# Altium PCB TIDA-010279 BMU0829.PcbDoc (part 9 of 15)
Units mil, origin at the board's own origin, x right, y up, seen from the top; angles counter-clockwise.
Board outline 11269.69 x 4438.98 mil, 4 copper layers (Top Layer, Signal Layer 1, Signal Layer 2, Bottom Layer), stack 61.6 mil thick; 1494 components, 725 nets, 3766 pads, 2728 vias.
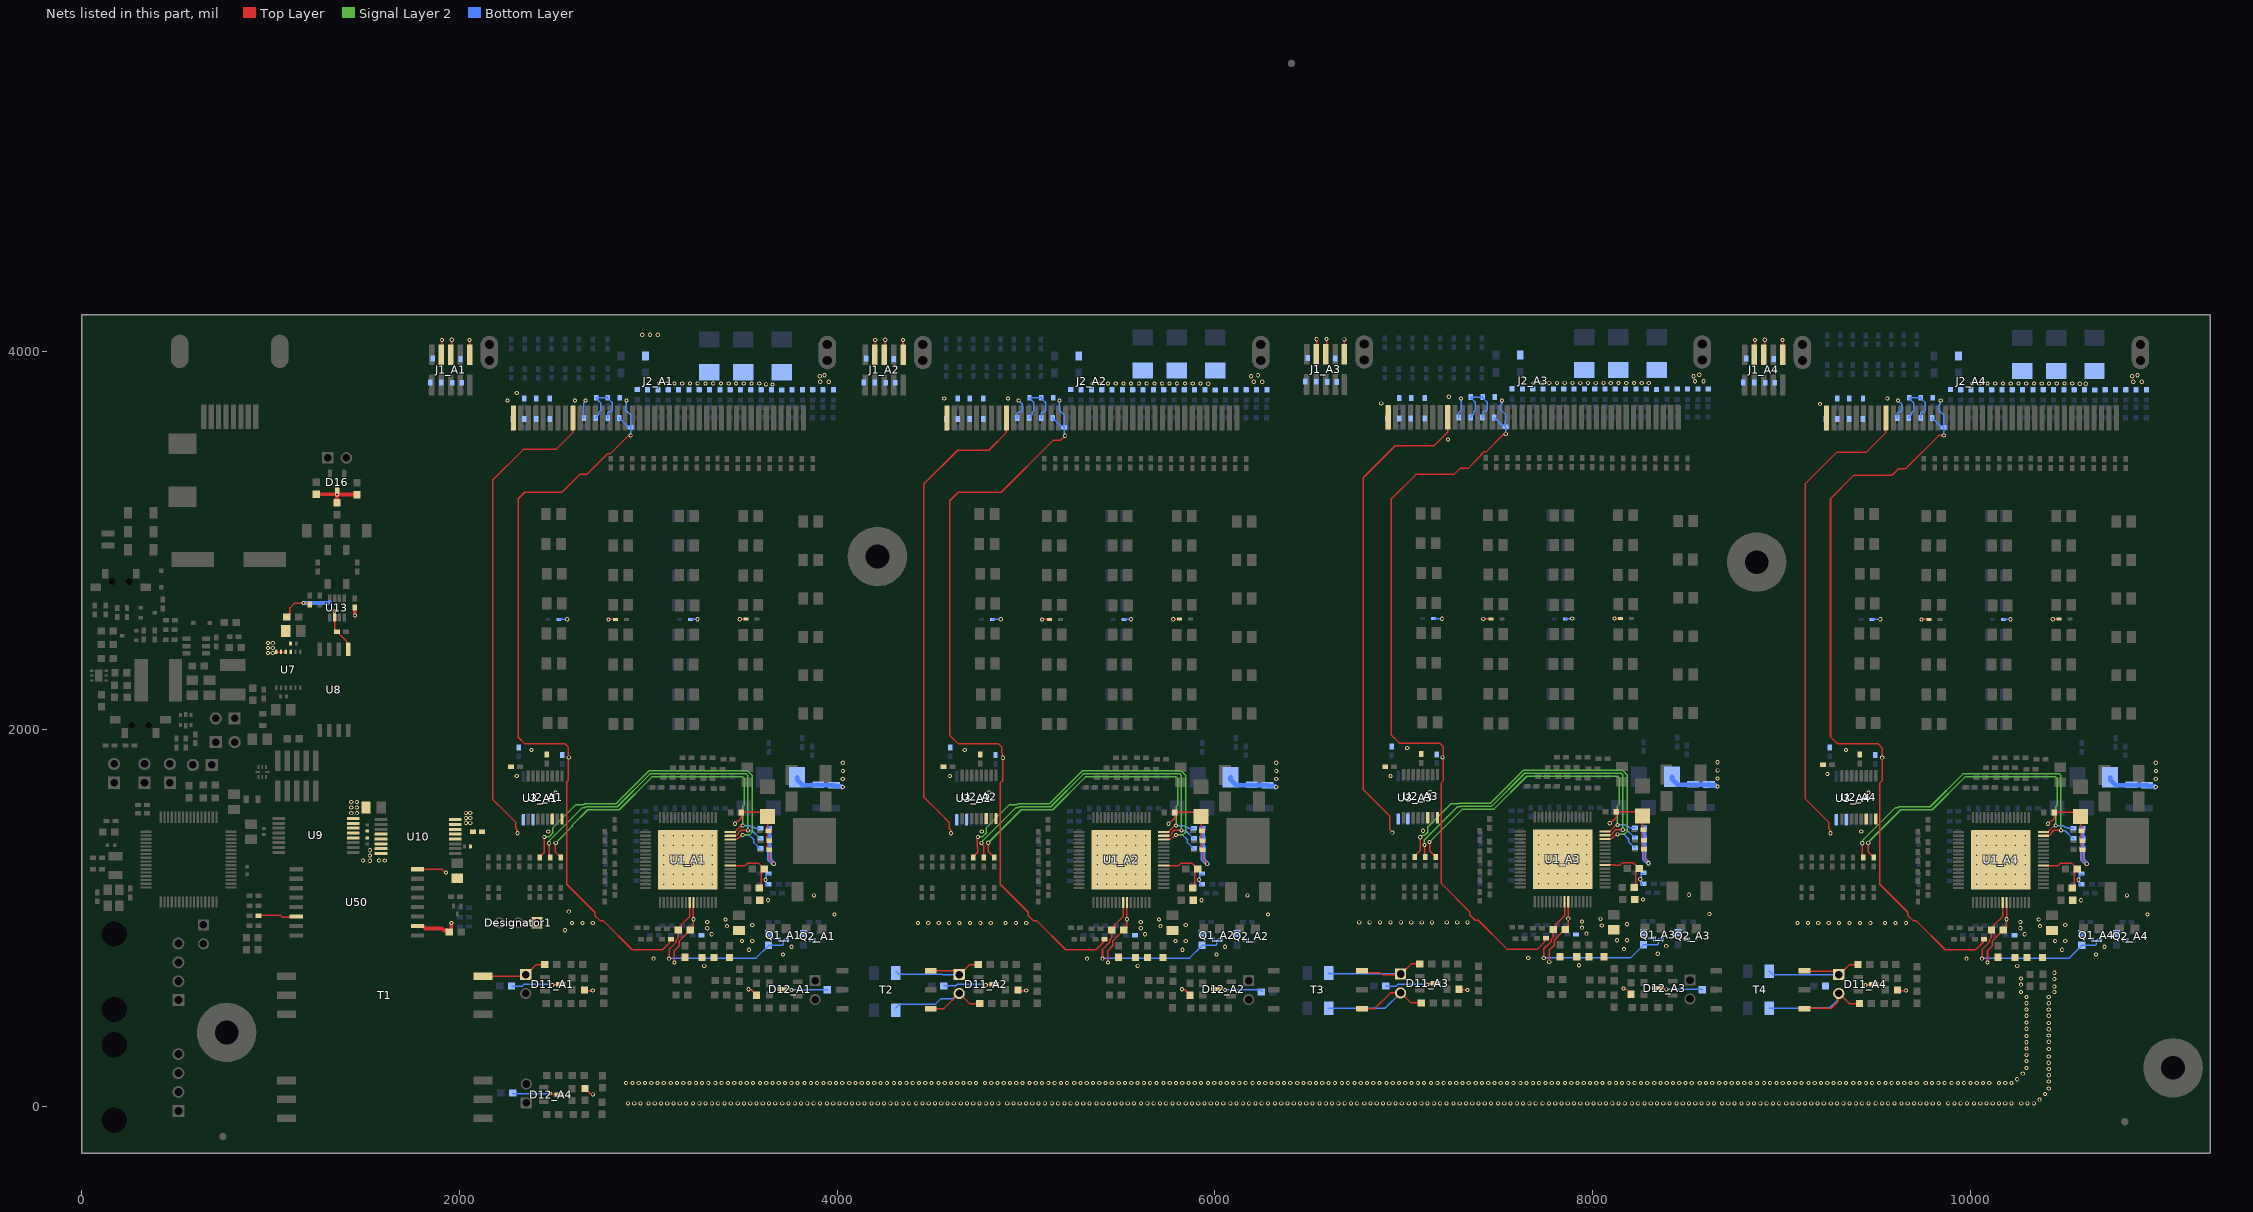
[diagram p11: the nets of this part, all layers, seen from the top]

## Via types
v1: diameter 22.01, hole 12.01, Top Layer to Bottom Layer, tented both sides, 2578 vias
v2: diameter 19.68, hole 7.87, Top Layer to Bottom Layer, tented both sides, 144 vias
v3: diameter 92.52, hole 49.21, Top Layer to Bottom Layer, 4 vias
v4: diameter 19.68, hole 7.87, Top Layer to Bottom Layer, 2 vias

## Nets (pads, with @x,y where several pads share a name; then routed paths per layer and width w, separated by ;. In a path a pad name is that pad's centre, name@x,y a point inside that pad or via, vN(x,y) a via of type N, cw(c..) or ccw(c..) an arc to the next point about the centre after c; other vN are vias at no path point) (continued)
COMML_N_OPT_A2: C163.2 J3_A2.2 R190_A2.1 T2.4 | length 683.8
  Top Layer w8: T2.4@4495.57,520.08 4565.69,520.08 4645.67,600.06 J3_A2.2@4645.67,600.39 ; J3_A2.2@4646.9,600.87 4701.1,546.67 R190_A2.1@4755.58,546.67
  Bottom Layer w8: C163.2@4311.02,521.65 4311.02,524.61 4330.65,544.23 4520.61,544.23 4549.52,573.15 4614.27,573.15 4641.39,600.27 J3_A2.2@4645.87,600.27
COMML_N_OPT_A3: C164.2 J3_A3.2 R190_A3.1 T3.4 | length 789.4
  Top Layer w8: T3.4@6779.04,520.08 6845.75,520.08 6929.15,603.48 6975.26,603.48 J3_A3.2@6978.35,600.39 ; J3_A3.2@6983.49,604.08 7037.7,549.88 R190_A3.1@7092.18,549.88
  Bottom Layer w8: C164.2@6602.36,521.65 6900.65,521.65 J3_A3.2@6982.47,603.48 6988.19,609.19 J3_A3.2@6988.19,610.24
COMML_N_OPT_A4: C165.2 J3_A4.2 R190_A4.1 T4.4 | length 798.4
  Top Layer w8: T4.4@9121.56,520.08 9123.13,521.65 9263.23,521.65 9300.31,558.74 9300.31,599.53 J3_A4.2@9311.02,610.24 ; J3_A4.2@9303.72,600.87 9357.93,546.67 R190_A4.1@9412.41,546.67
  Bottom Layer w8: C165.2@8935.04,521.65 9251.97,521.65 9295.28,564.96 9295.28,592.84 J3_A4.2@9302.7,600.27
COMML_P_OPT_A1: J3_A1.1 R177_A1.1 T1.6 | length 343
  Top Layer w8: T1.6@2135.83,688.98 2137.57,690.71 2341.32,690.71 J3_A1.1@2350.88,700.27 ; J3_A1.1@2351.24,700.63 2376.4,725.8 2379.34,725.8 2406.91,753.36 R177_A1.1@2452.69,753.36
COMML_P_OPT_A2: C153.1 J3_A2.1 R177_A2.1 T2.6 | length 621.1
  Top Layer w8: T2.6@4495.57,720.08 4620.35,720.08 4635.83,704.6 J3_A2.1@4635.83,698.82 ; J3_A2.1@4646.25,697.69 4646.25,700.63 4671.42,725.8 4674.36,725.8 4701.92,753.36 R177_A2.1@4747.7,753.36
  Bottom Layer w8: C153.1@4311.02,718.5 4327.52,702.01 4553.89,702.01 4555.64,700.27 J3_A2.1@4645.87,700.27
COMML_P_OPT_A3: C154.1 J3_A3.1 R177_A3.1 T3.6 | length 734.1
  Top Layer w8: T3.6@6779.04,720.08 6788.05,711.06 6874.5,711.06 6886.74,698.82 J3_A3.1@6988.19,698.82 ; J3_A3.1@6982.85,700.9 6982.85,703.84 7008.02,729 7010.95,729 7038.52,756.57 R177_A3.1@7084.3,756.57
  Bottom Layer w8: C154.1@6602.36,708.66 6607.55,703.48 J3_A3.1@6982.47,703.48 6983.53,703.48 J3_A3.1@6988.19,698.82
COMML_P_OPT_A4: C155.1 J3_A4.1 R177_A4.1 T4.6 | length 699.9
  Top Layer w8: T4.6@9121.56,720.08 9124.24,717.4 9282.6,717.4 J3_A4.1@9311.02,688.98 ; J3_A4.1@9303.08,700.63 9328.25,725.8 9331.18,725.8 9358.75,753.36 R177_A4.1@9404.53,753.36
  Bottom Layer w8: C155.1@8935.04,718.5 8953.27,700.27 9299.73,700.27 J3_A4.1@9301.18,698.82
DDGND: C202.2 C203.1 C204.2 C218.2 C219.2 C220.1 C221.1 C222.2 D16.3 R256.2 U7.9 U7.10 U7.11 U7.12 U8.5 U13.2 | length 958.1
  Top Layer w8: U7.12@1029.53,2408.32 1029.53,2408.07 1031.44,2406.16 1053.22,2406.16 1055.12,2408.07 U7.11@1055.12,2408.32 ; U7.11@1055.78,2405.95 1055.99,2406.16 1078.81,2406.16 1080.72,2408.07 U7.10@1080.72,2408.32 ; C204.2@1079.53,2504.6 C204.2@1079.53,2518.39 C204.2@1079.53,2524.89 ; C202.2@1086.46,2593.41 1087.45,2593.41 1102.15,2608.11 1102.15,2641.33 1127.09,2666.27 1173.55,2666.27 v1(1174.7,2667.42) 1199.36,2667.42 R256.2@1206.74,2660.04 ; v1@1338.81,2623.74 U13.2@1338.81,2590.08 1338.81,2528.26 1339.7,2527.37 1339.7,2523.44 1347.51,2515.62 C220.1@1351.45,2515.62 1355.39,2515.62 1363.2,2507.81 1363.2,2503.88 1402.39,2464.68 1402.39,2429.72 U8.5@1410.2,2421.91 ; C219.2@1359.32,3206.27 1368.2,3197.4 C219.2@1368.2,3196.41
  Top Layer w20: C204.2@1079.53,2504.6 C204.2@1086.06,2498.06 ; C218.2@1241.81,3243.07 1343.55,3243.07 1351.97,3251.49 D16.3@1351.97,3259.37 ; v1(1338.49,2624.06) v1@1338.81,2623.74 ; v1(1351.61,3241.65) 1351.79,3241.83 1351.79,3241.65 D16.3@1351.97,3241.65 ; C219.2@1351.97,3198.92 D16.3@1351.97,3241.65 ; v1(1446.1,2601.44) C222.2@1446.1,2644.37 ; C221.1@1454.96,3244.76 1452.32,3244.76 1449.21,3241.65 D16.3@1351.97,3241.65
  Bottom Layer w20: v1(1174.7,2667.42) 1174.8,2667.32 1304.87,2667.32 1311.28,2673.74
  other v1: 986.45,2403.38 1011.57,2402.93 986.45,2429.24 1011.57,2428.79 1011.57,2455.05 986.45,2455.98
DVDD_A1: C38_A1.2 Q1_A1.1 R136_A1.2 U1_A1.41 | length 1025.4
  Top Layer w8: v1(3109.49,784.63) 3109.49,833.54 3148.4,872.44 3148.4,885.1 3159.35,896.06 C38_A1.2@3159.35,936.51 3173.12,950.28 3173.12,962.09 3219.31,1008.28 U1_A1.41@3219.31,1082.55
  Bottom Layer w8: v1(3109.49,784.63) 3112.17,787.31 3570.71,787.31 3637.22,853.82 R136_A1.2@3637.22,854.81 3710.11,854.81 3715.29,859.99 3715.29,881.62 3719.97,886.3 Q1_A1.1@3736.09,886.3
DVDD_A2: C38_A2.2 Q1_A2.1 R136_A2.2 U1_A2.41 | length 1025.4
  Top Layer w8: v1(5404.51,784.63) 5404.51,833.54 5443.41,872.44 5443.41,885.1 5454.36,896.06 C38_A2.2@5454.36,936.51 5468.14,950.28 5468.14,962.09 5514.33,1008.28 U1_A2.41@5514.33,1082.55
  Bottom Layer w8: v1(5404.51,784.63) 5407.19,787.31 5865.73,787.31 5932.24,853.82 R136_A2.2@5932.24,854.81 6005.12,854.81 6010.3,859.99 6010.3,881.62 6014.99,886.3 Q1_A2.1@6031.11,886.3
DVDD_A3: C38_A3.2 Q1_A3.1 R136_A3.2 U1_A3.41 | length 1025.4
  Top Layer w8: v1(7741.11,787.84) 7741.11,836.75 7780.01,875.65 7780.01,888.31 7790.96,899.26 C38_A3.2@7790.96,939.71 7804.73,953.49 7804.73,965.3 7850.92,1011.49 U1_A3.41@7850.92,1085.75
  Bottom Layer w8: v1(7741.11,787.84) 7743.79,790.52 8202.32,790.52 8268.83,857.03 R136_A3.2@8268.83,858.01 8341.72,858.01 8346.9,863.2 8346.9,884.82 8351.59,889.51 Q1_A3.1@8367.7,889.51
DVDD_A4: C38_A4.2 Q1_A4.1 R136_A4.2 U1_A4.41 | length 1025.4
  Top Layer w8: v1(10061.34,784.63) 10061.34,833.54 10100.24,872.44 10100.24,885.1 10111.19,896.06 C38_A4.2@10111.19,936.51 10124.96,950.28 10124.96,962.09 10171.15,1008.28 U1_A4.41@10171.15,1082.55
  Bottom Layer w8: v1(10061.34,784.63) 10064.02,787.31 10522.55,787.31 10589.06,853.82 R136_A4.2@10589.06,854.81 10661.95,854.81 10667.13,859.99 10667.13,881.62 10671.82,886.3 Q1_A4.1@10687.93,886.3
FAULT2AFE: R250.1 U50.14 | length 179.1
  Top Layer w8: R250.1@937.69,1013.54 937.96,1013.81 1053.12,1013.81 1062.99,1003.94 U50.14@1112.59,1003.94
GND_A1: C6_A1.2 C9_A1.2 C12_A1.2 C18_A1.1 C20_A1.2 C24_A1.2 C26_A1.1 C28_A1.2 C32_A1.2 C38_A1.1 C40_A1.2 C43_A1.2 C46_A1.1 C48_A1.2 C51_A1.2 C55_A1.1 C57_A1.2 C60_A1.2 C64_A1.1 C66_A1.2 C70_A1.2 C78_A1.2 C83_A1.2 C87_A1.2 C92_A1.2 C100_A1.2 C103_A1.2 C107_A1.2 C108_A1.2 C109_A1.2 C110_A1.2 C111_A1.2 C112_A1.2 C113_A1.2 C114_A1.2 C115_A1.1 C116_A1.2 C117_A1.2 C118_A1.2 C119_A1.2 C120_A1.2 C121_A1.2 C122_A1.2 C123_A1.2 C124_A1.2 C125_A1.1 C126_A1.2 C127_A1.2 C128_A1.2 C129_A1.2 C130_A1.2 C131_A1.2 C132_A1.2 C133_A1.2 C135_A1.1 C136_A1.2 C137_A1.2 C138_A1.2 C140_A1.2 C147_A1.1 C148_A1.2 C149_A1.2 C150_A1.2 C151_A1.2 C152_A1.2 C156.1 C157.1 C191_A1.1 D4_A1.2 D6_A1.2 D7_A1.2 D8_A1.2 D9_A1.2 D10_A1.2 D11_A1.3 D12_A1.3 Designator1.1 J1_A1.4 J1_A1.6 J1_A1.10 J2_A1.21 J2_A1.25 Q1_A1.2 Q2_A1.2 R136_A1.1 R137_A1.1 R140_A1.1 R148_A1.1 R151_A1.1 R211.1 RT1_A1.2 RT2_A1.2 RT3_A1.2 RT4_A1.2 U1_A1.42 U1_A1.55 U1_A1.65 U2_A1.6 U2_A1.8 U3_A1.6 U3_A1.8 | length 9869.8
  Top Layer w8: J1_A1.4@1906.73,3974.78 v1(1906.73,4060.48) ; J1_A1.6@1953.97,3981.48 1959.19,3986.71 v1(1959.19,4061.75) ; J1_A1.6@1957.63,3972.94 J1_A1.6@1957.95,3972.62 ; v1(2053.29,4060.32) 2053.29,3977.28 J1_A1.10@2054.4,3976.17 ; v1(2307.64,1448.63) 2306.75,1449.53 2306.75,1464.2 2298.59,1472.36 2298.59,1505.37 2246.25,1557.71 2175.5,1628.46 2175.5,3317.24 2338.87,3480.6 2510.94,3480.6 2600.5,3570.16 J2_A1.25@2600.5,3647.12 ; 2311.37,3022.31 2311.37,1956.37 2346.42,1921.32 2560.1,1921.32 2575.89,1905.52 2575.89,1850.39 2575.89,1727.17 2567.64,1718.91 2567.64,1178.7 2716.54,1029.8 2716.54,1013.78 2746.06,984.25 2762.08,984.25 2914.58,831.76 3075.33,831.76 3115.4,871.83 3115.4,883.8 C107_A1.2@3120.11,888.51 ; 2311.38,3022.31 2311.38,3219.23 2346.23,3254.09 2543.15,3254.09 2637.76,3348.69 2674.66,3348.69 2784.84,3458.88 2799.43,3458.88 2892.8,3552.25 2903.65,3552.25 v1(2906.33,3554.93) ; v1(2491.9,644.99) 2494.47,647.56 2537.32,647.56 D11_A1.3@2539.37,649.61 ; C147_A1.1@2661.35,618.63 2664.06,615.92 2702.54,615.92 v1@2706.69,620.08 ; v1(2789,2580.3) RT1_A1.2@2825.65,2580.3 ; v1(3138.28,764.43) 3138.28,826.77 3164.27,852.76 3164.27,878.53 3175.22,889.48 3175.22,890.37 3221.36,936.51 C38_A1.1@3222.34,936.51 3223.32,936.51 3238.03,951.21 3238.03,992.2 v1(3239,993.17) U1_A1.42@3239,1082.55 ; v1@3260.13,2581.77 v1(3260.18,2581.72) ; U1_A1.55@3433.88,1277.43 3484.4,1277.43 3485.81,1276.02 3512.18,1276.02 3526.58,1290.42 3582.61,1290.42 3612.2,1260.83 C64_A1.1@3612.2,1259.84 ; v1@3454.72,1496.06 3456.87,1496.06 3475.12,1514.32 3479.2,1514.32 3492.28,1527.4 C26_A1.1@3492.28,1558.6 3610.45,1558.6 D9_A1.2@3631.54,1537.51 3631.54,1462.99 3631.54,1368.46 3639.35,1360.65 C135_A1.1@3640.15,1360.65 3640.15,1310.21 3660.99,1289.37 v1@3661.42,1289.37 ; v1(3483.99,2581.94) 3484.21,2582.16 3516.07,2582.16 RT4_A1.2@3516.3,2582.39 ; v1(3530.76,622.88) 3533.44,620.2 3544.42,620.2 3571.8,592.82 C148_A1.2@3571.8,591.84 ; C46_A1.1@3582.68,1161.42 3585.83,1161.42 3597.2,1172.79 3597.2,1242.87 3598.49,1244.16 3598.49,1245.14 3613.19,1259.84 C64_A1.1@3614.17,1259.84 ; D12_A1.3@3689.24,615.92 3697.05,623.73 D12_A1.3@3708.82,623.73 3711.24,621.31 3758.61,621.31 v1@3759.84,620.08
  Bottom Layer w8: C156.1@2275.59,639.76 2331.82,639.76 2341.66,649.61 v1@2500,649.61 ; RT2_A1.2@2525.97,2581.17 v1(2571.04,2581.17) ; C137_A1.2@2659.32,3645.96 2659.32,3728.37 2667.32,3736.37 v1(2667.32,3740.16) ; C127_A1.2@2721.82,3645.96 2721.82,3649.9 2738.3,3666.38 2738.3,3673.88 2738.49,3674.08 2738.49,3678.01 2746.8,3686.32 2746.8,3727.65 2731.97,3742.48 2730.93,3742.48 2723.12,3750.29 C131_A1.2@2723.12,3754.23 C122_A1.2@2779.82,3754.23 ; C117_A1.2@2784.32,3645.96 2785.82,3647.46 2785.82,3673.71 2791.47,3679.37 2802.55,3679.37 2809.5,3686.32 2809.5,3727.65 2794.67,3742.48 2793.63,3742.48 2785.82,3750.29 C122_A1.2@2785.82,3754.23 C122_A1.2@2779.82,3754.23 ; C122_A1.2@2785.43,3759.84 C122_A1.2@2779.82,3754.23 ; v1(2789,2580.3) v1@2789.62,2580.92 ; C109_A1.2@2846.81,3649.9 C109_A1.2@2846.81,3645.96 2846.81,3642.03 2854.62,3634.22 2858.56,3634.22 2887.2,3605.58 2898.52,3605.58 R140_A1.1@2906.33,3597.76 ; v1(2883.85,3740.15) 2883.85,3712.68 2880.63,3709.45 2880.63,3688.45 2906.78,3662.29 2906.78,3626.88 2906.33,3626.43 R140_A1.1@2906.33,3597.76 ; v1(2906.33,3554.93) R140_A1.1@2906.33,3597.76 ; RT3_A1.2@3222.89,2580.76 3223.37,2581.24 3255.37,2581.24 v1@3257.87,2578.74 ; C110_A1.2@3631.89,1171.26 3625.34,1177.81 3625.34,1193.04 3620.21,1198.17 v1(3620.21,1201.96) 3620.21,1205.75 3625.34,1210.88 3625.34,1227.55 3628.1,1230.32 C114_A1.2@3641.73,1230.32 ; R136_A1.1@3637.22,917.8 3637.22,916.81 3667.73,886.3 Q1_A1.2@3695.93,886.3 ; v1(3757.94,618.89) 3945.66,618.89 C157.1@3946.85,620.08 ; R137_A1.1@3821,917.8 3821,916.81 R137_A1.1@3835.7,902.11 ; v1@3858.27,885.83 3859.44,887 3873.69,887 3877.17,883.52 Q2_A1.2@3877.17,881.62
  Bottom Layer w25: C129_A1.2@3640.15,1377.95 C124_A1.2@3640.15,1422.9 C119_A1.2@3640.15,1474.8 ; C129_A1.2@3641.73,1377.95 3641.73,1308.62 v1(3663.91,1286.45) ; D10_A1.2@3787.71,1744.01 3787.71,1732.76 3817.71,1702.76 C191_A1.1@3983.15,1702.76 ; C191_A1.1@3983.15,1703.25 3988.37,1698.04 4020.47,1698.04 v1@4025.59,1692.91
  other v1: 2705.95,615.92 3295.7,746.4 3027.11,784.63 3712.75,807.09 3533.44,831.76 3758,847.63 3496.48,878.53 3550.27,878.53 3856.43,887 3335.07,913.72 2559.06,935.04 3312.21,945.67 3416.34,956.82 3549.89,963.13 2595.73,973.59 2650.84,973.59 2705.95,973.59 3312.21,978.59 3409.05,992.2 3985.88,1018.27 2578.74,1033.46 3634.09,1094.07 3877.43,1119.64 2469.96,1458.36 3458.36,1498.55 2507.98,1663.75 4029.16,1692.97 4029.16,1735.46 2303.15,1751.97 4029.89,1778.44 4029.16,1821.64 2578.74,1850.39 2381.89,1889.76 2253.94,3740.16 2611.46,3740.16 2303.15,3779.53 3623.68,3825.06 3657.63,3824.8 3463.66,3829.44 3504.76,3829.44 3545.86,3829.44 3586.96,3829.44 3056.19,3829.78 3097.29,3829.78 3138.39,3829.78 3179.49,3829.78 3220.59,3829.78 3261.01,3829.78 3302.11,3829.78 3343.22,3829.78 3384.32,3829.78 3425.42,3829.78 3910.1,3838.58 3955.07,3838.58 3907.48,3868.11 3932.1,3873.08 2967.59,4088.02 3008.69,4088.02 3049.79,4088.02
  other v2: 3081.51,1179 3132.7,1179 3183.88,1179 3235.06,1179 3286.24,1179 3337.42,1179 3081.51,1230.18 3132.7,1230.18 3183.88,1230.18 3235.06,1230.18 3286.24,1230.18 3337.42,1230.18 3081.51,1281.37 3132.7,1281.37 3183.88,1281.37 3235.06,1281.37 3286.24,1281.37 3337.42,1281.37 3081.51,1332.55 3132.7,1332.55 3183.88,1332.55 3235.06,1332.55 3286.24,1332.55 3337.42,1332.55 3081.51,1383.73 3132.7,1383.73 3183.88,1383.73 3235.06,1383.73 3286.24,1383.73 3337.42,1383.73 3081.51,1434.91 3132.7,1434.91 3183.88,1434.91 3235.06,1434.91 3286.24,1434.91 3337.42,1434.91
GND_A2: C6_A2.2 C9_A2.2 C12_A2.2 C18_A2.1 C20_A2.2 C24_A2.2 C26_A2.1 C28_A2.2 C32_A2.2 C38_A2.1 C40_A2.2 C43_A2.2 C46_A2.1 C48_A2.2 C51_A2.2 C55_A2.1 C57_A2.2 C60_A2.2 C64_A2.1 C66_A2.2 C70_A2.2 C78_A2.2 C83_A2.2 C87_A2.2 C92_A2.2 C100_A2.2 C103_A2.2 C107_A2.2 C108_A2.2 C109_A2.2 C110_A2.2 C111_A2.2 C112_A2.2 C113_A2.2 C114_A2.2 C115_A2.1 C116_A2.2 C117_A2.2 C118_A2.2 C119_A2.2 C120_A2.2 C121_A2.2 C122_A2.2 C123_A2.2 C124_A2.2 C125_A2.1 C126_A2.2 C127_A2.2 C128_A2.2 C129_A2.2 C130_A2.2 C131_A2.2 C132_A2.2 C133_A2.2 C135_A2.1 C136_A2.2 C137_A2.2 C138_A2.2 C140_A2.2 C147_A2.1 C148_A2.2 C149_A2.2 C150_A2.2 C151_A2.2 C152_A2.2 C158.1 C159.1 C191_A2.1 D4_A2.2 D6_A2.2 D7_A2.2 D8_A2.2 D9_A2.2 D10_A2.2 D11_A2.3 D12_A2.3 J1_A2.4 J1_A2.6 J1_A2.10 J2_A2.21 J2_A2.25 Q1_A2.2 Q2_A2.2 R136_A2.1 R137_A2.1 R140_A2.1 R148_A2.1 R151_A2.1 RT1_A2.2 RT2_A2.2 RT3_A2.2 RT4_A2.2 U1_A2.42 U1_A2.55 U1_A2.65 U2_A2.6 U2_A2.8 U3_A2.6 U3_A2.8 | length 9933.4
  Top Layer w8: J1_A2.4@4201.75,3974.78 v1(4201.75,4060.48) ; J1_A2.6@4248.99,3981.48 4254.21,3986.71 v1(4254.21,4061.75) ; J1_A2.6@4252.64,3972.94 J1_A2.6@4252.96,3972.62 ; v1(4348.31,4060.32) 4348.31,3977.28 J1_A2.10@4349.42,3976.17 ; v1(4602.66,1448.63) 4601.77,1449.53 4601.77,1464.2 4593.61,1472.36 4593.61,1505.37 4541.27,1557.71 4458.66,1640.32 4458.66,3297.24 4637.98,3476.56 4801.91,3476.56 4895.52,3570.16 J2_A2.25@4895.52,3647.12 ; v1(4786.92,644.99) 4789.48,647.56 4832.34,647.56 D11_A2.3@4834.39,649.61 ; C147_A2.1@4956.37,618.63 4959.08,615.92 4997.55,615.92 v1@5001.71,620.08 ; v1(5084.02,2580.3) RT1_A2.2@5120.66,2580.3 ; v1(5206.69,3553.15) 5183.81,3530.27 5144.44,3530.27 4868.26,3254.09 4641.24,3254.09 4595.98,3208.82 4595.98,1966.78 4641.44,1921.32 4855.11,1921.32 4870.91,1905.52 4870.91,1875.63 4874.91,1871.63 4874.91,1850.56 v1(4876.85,1848.62) 4876.85,1728.08 4862.65,1713.89 4862.65,1178.7 5011.55,1029.8 5011.55,1013.78 5041.08,984.25 5057.1,984.25 5209.59,831.76 5370.35,831.76 5410.42,871.83 5410.42,883.8 C107_A2.2@5415.12,888.51 ; v1(5433.29,764.43) 5433.29,826.77 5459.29,852.76 5459.29,878.53 5470.24,889.48 5470.24,890.37 5516.37,936.51 C38_A2.1@5517.36,936.51 5518.34,936.51 5533.04,951.21 5533.04,992.2 v1(5534.01,993.17) U1_A2.42@5534.01,1082.55 ; v1@5555.14,2581.77 v1(5555.2,2581.72) ; U1_A2.55@5728.89,1277.43 5779.42,1277.43 5780.83,1276.02 5807.2,1276.02 5821.59,1290.42 5877.63,1290.42 5907.22,1260.83 C64_A2.1@5907.22,1259.84 ; v1@5749.74,1496.06 5751.89,1496.06 5770.14,1514.32 5774.21,1514.32 5787.3,1527.4 C26_A2.1@5787.3,1558.6 5905.47,1558.6 5926.55,1537.51 5926.55,1368.46 5934.36,1360.65 C135_A2.1@5935.16,1360.65 5935.16,1310.21 5956,1289.37 v1@5956.43,1289.37 ; v1(5779,2581.94) 5779.23,2582.16 5811.09,2582.16 RT4_A2.2@5811.31,2582.39 ; v1(5825.78,622.88) 5828.46,620.2 5839.44,620.2 5866.81,592.82 C148_A2.2@5866.81,591.84 ; C46_A2.1@5877.69,1161.42 5880.85,1161.42 5892.22,1172.79 5892.22,1242.87 5893.5,1244.16 5893.5,1245.14 5908.2,1259.84 C64_A2.1@5909.19,1259.84 ; D12_A2.3@5984.25,615.92 5992.06,623.73 D12_A2.3@6003.83,623.73 6006.26,621.31 6053.63,621.31 v1@6054.86,620.08
  Bottom Layer w8: C158.1@4564.22,640.91 4627.96,640.91 4636.66,649.61 v1@4793.31,649.61 ; RT2_A2.2@4820.98,2581.17 v1(4866.05,2581.17) ; C137_A2.2@4954.34,3645.96 4954.34,3673.71 4959.99,3679.37 4972.17,3679.37 4979.12,3686.32 4979.12,3721.66 v1(4960.63,3740.16) ; C127_A2.2@5016.84,3645.96 5016.84,3649.9 5033.31,3666.38 5033.31,3673.88 5033.51,3674.08 5033.51,3678.01 5041.82,3686.32 5041.82,3727.65 5026.99,3742.48 5025.95,3742.48 5018.14,3750.29 C131_A2.2@5018.14,3754.23 C122_A2.2@5074.84,3754.23 ; C117_A2.2@5079.33,3645.96 5080.83,3647.46 5080.83,3673.71 5086.49,3679.37 5097.56,3679.37 5104.52,3686.32 5104.52,3727.65 5089.69,3742.48 5088.64,3742.48 5080.83,3750.29 C122_A2.2@5080.83,3754.23 C122_A2.2@5074.84,3754.23 ; C122_A2.2@5080.45,3759.84 C122_A2.2@5074.84,3754.23 ; v1(5084.02,2580.3) v1@5084.63,2580.92 ; C109_A2.2@5141.83,3649.9 C109_A2.2@5141.83,3645.96 5141.83,3642.03 5149.64,3634.22 5153.57,3634.22 5182.21,3605.58 5193.53,3605.58 R140_A2.1@5201.34,3597.76 ; v1(5177.15,3740.15) 5175.64,3738.64 5175.64,3688.45 5201.8,3662.29 5201.8,3626.88 5201.34,3626.43 R140_A2.1@5201.34,3597.76 ; v1(5206.69,3553.15) 5206.69,3556.94 5201.34,3562.29 R140_A2.1@5201.34,3597.76 ; RT3_A2.2@5517.9,2580.76 5518.38,2581.24 5550.39,2581.24 v1@5552.89,2578.74 ; C110_A2.2@5926.91,1171.26 5920.35,1177.81 5920.35,1193.04 5915.22,1198.17 v1(5915.22,1201.96) 5915.22,1205.75 5920.35,1210.88 5920.35,1227.55 5923.11,1230.32 C114_A2.2@5936.75,1230.32 ; R136_A2.1@5932.24,917.8 5932.24,916.81 5962.75,886.3 Q1_A2.2@5990.95,886.3 ; v1(6052.95,618.89) 6241.35,618.89 C159.1@6250,610.24 ; R137_A2.1@6116.01,917.8 6116.01,916.81 R137_A2.1@6130.71,902.11 ; v1@6153.28,885.83 6154.46,887 6168.7,887 6172.18,883.52 Q2_A2.2@6172.18,881.62
  Bottom Layer w25: C129_A2.2@5935.16,1377.95 C124_A2.2@5935.16,1422.9 C119_A2.2@5935.16,1474.8 ; C129_A2.2@5936.75,1377.95 5936.75,1308.62 v1(5958.92,1286.45) ; D10_A2.2@6082.72,1744.01 6082.73,1732.76 6112.73,1702.76 C191_A2.1@6278.17,1702.76 ; C191_A2.1@6278.17,1703.25 6283.39,1698.04 6315.48,1698.04 v1@6320.61,1692.91
  other v1: 5000.97,615.92 5590.72,746.4 5322.13,784.63 6007.77,807.09 5828.46,831.76 6053.02,847.63 5791.5,878.53 5845.29,878.53 6151.44,887 5630.09,913.72 5607.23,945.67 5711.35,956.82 5844.91,963.13 4427.22,973.59 4482.33,973.59 4537.44,973.59 4592.55,973.59 4647.66,973.59 4702.78,973.59 4757.89,973.59 4813,973.59 4890.75,973.59 4945.86,973.59 5000.97,973.59 5607.23,978.59 5704.07,992.2 6280.9,1018.27 5929.1,1094.07 6172.45,1119.64 4764.97,1458.36 5753.37,1498.55 4803,1663.75 6324.18,1692.97 6324.18,1735.46 4596.46,1751.97 6324.9,1778.44 6324.18,1821.64 4675.2,1889.76 4566.93,3750 4904.27,3750 5758.67,3829.44 5799.77,3829.44 5840.87,3829.44 5881.98,3829.44 5923.08,3829.44 5964.57,3828.74 5351.21,3829.78 5392.31,3829.78 5433.41,3829.78 5474.51,3829.78 5515.61,3829.78 5556.03,3829.78 5597.13,3829.78 5638.23,3829.78 5679.33,3829.78 5720.43,3829.78 6205.12,3838.58 6250.08,3838.58 6190.94,3868.11 6227.12,3873.08
  other v2: 5376.53,1179 5427.71,1179 5478.89,1179 5530.07,1179 5581.26,1179 5632.44,1179 5376.53,1230.18 5427.71,1230.18 5478.89,1230.18 5530.07,1230.18 5581.26,1230.18 5632.44,1230.18 5376.53,1281.37 5427.71,1281.37 5478.89,1281.37 5530.07,1281.37 5581.26,1281.37 5632.44,1281.37 5376.53,1332.55 5427.71,1332.55 5478.89,1332.55 5530.07,1332.55 5581.26,1332.55 5632.44,1332.55 5376.53,1383.73 5427.71,1383.73 5478.89,1383.73 5530.07,1383.73 5581.26,1383.73 5632.44,1383.73 5376.53,1434.91 5427.71,1434.91 5478.89,1434.91 5530.07,1434.91 5581.26,1434.91 5632.44,1434.91
GND_A3: C6_A3.2 C9_A3.2 C12_A3.2 C18_A3.1 C20_A3.2 C24_A3.2 C26_A3.1 C28_A3.2 C32_A3.2 C38_A3.1 C40_A3.2 C43_A3.2 C46_A3.1 C48_A3.2 C51_A3.2 C55_A3.1 C57_A3.2 C60_A3.2 C64_A3.1 C66_A3.2 C70_A3.2 C78_A3.2 C83_A3.2 C87_A3.2 C92_A3.2 C100_A3.2 C103_A3.2 C107_A3.2 C108_A3.2 C109_A3.2 C110_A3.2 C111_A3.2 C112_A3.2 C113_A3.2 C114_A3.2 C115_A3.1 C116_A3.2 C117_A3.2 C118_A3.2 C119_A3.2 C120_A3.2 C121_A3.2 C122_A3.2 C123_A3.2 C124_A3.2 C125_A3.1 C126_A3.2 C127_A3.2 C128_A3.2 C129_A3.2 C130_A3.2 C131_A3.2 C132_A3.2 C133_A3.2 C135_A3.1 C136_A3.2 C137_A3.2 C138_A3.2 C140_A3.2 C147_A3.1 C148_A3.2 C149_A3.2 C150_A3.2 C151_A3.2 C152_A3.2 C160.1 C161.1 C191_A3.1 D4_A3.2 D6_A3.2 D7_A3.2 D8_A3.2 D9_A3.2 D10_A3.2 D11_A3.3 D12_A3.3 J1_A3.4 J1_A3.6 J1_A3.10 J2_A3.21 J2_A3.25 Q1_A3.2 Q2_A3.2 R136_A3.1 R137_A3.1 R140_A3.1 R148_A3.1 R151_A3.1 RT1_A3.2 RT2_A3.2 RT3_A3.2 RT4_A3.2 U1_A3.42 U1_A3.55 U1_A3.65 U2_A3.6 U2_A3.8 U3_A3.6 U3_A3.8 | length 9918.3
  Top Layer w8: J1_A3.4@6538.34,3977.98 v1(6538.34,4063.69) ; J1_A3.6@6585.58,3984.69 6590.81,3989.92 v1(6590.81,4064.96) ; J1_A3.6@6589.24,3976.15 J1_A3.6@6589.56,3975.83 ; v1(6684.9,4063.53) 6684.9,3980.49 J1_A3.10@6686.02,3979.38 ; v1(6939.26,1451.84) 6939.26,1454.49 6924.31,1469.43 6924.31,1541.5 6785.15,1680.67 6785.15,3320.89 6785.15,3330.74 6954.7,3500.29 6964.54,3500.29 7159.03,3500.29 7232.11,3573.37 J2_A3.25@7232.11,3650.33 ; 7007.87,1889.76 v1(7017.72,1899.61) ; v1(7123.51,648.2) 7126.08,650.77 7168.94,650.77 D11_A3.3@7170.98,652.81 ; v1(7204.71,1850.39) v1@7207.5,1850.39 ; C147_A3.1@7292.96,621.84 7295.67,619.13 7334.15,619.13 v1@7338.31,623.29 ; v1(7420.61,2583.51) RT1_A3.2@7457.26,2583.51 ; v1(7539.37,3562.99) 7536.69,3560.31 7526.85,3560.31 7434.29,3467.76 7422.13,3467.76 7409.5,3455.13 7409.5,3450.75 7339.05,3380.3 7297.77,3380.3 7265.43,3347.96 7063.6,3347.96 6932.57,3216.93 6932.57,1969.91 6974.24,1928.25 6974.31,1928.25 6978.04,1924.52 7191.71,1924.52 7207.5,1908.73 v1@7207.5,1850.39 ; C107_A3.2@7751.72,891.71 7747.01,887.01 7747.01,875.04 7706.94,834.97 7546.19,834.97 7393.69,987.46 7377.68,987.46 7348.15,1016.99 7348.15,1033.01 7199.25,1181.9 7199.25,1717.1 7207.5,1725.35 v1@7207.5,1850.39 ; v1(7769.89,767.64) 7769.89,829.98 7795.88,855.97 7795.88,881.74 7806.83,892.69 7806.83,893.58 7852.97,939.71 C38_A3.1@7853.95,939.71 7854.94,939.71 7869.64,954.42 7869.64,995.41 v1(7870.61,996.38) U1_A3.42@7870.61,1085.75 ; v1@7891.74,2584.98 v1(7891.79,2584.93) ; U1_A3.55@8065.49,1280.64 8116.01,1280.64 8117.42,1279.23 8143.79,1279.23 8158.19,1293.63 8214.23,1293.63 8243.82,1264.04 C64_A3.1@8243.82,1263.05 ; v1@8086.34,1499.27 8088.48,1499.27 8106.74,1517.52 8110.81,1517.52 8123.9,1530.61 C26_A3.1@8123.9,1561.81 8242.07,1561.81 D9_A3.2@8263.14,1540.72 8263.15,1371.67 8270.96,1363.85 C135_A3.1@8271.76,1363.85 8271.76,1313.42 8292.6,1292.58 v1@8293.03,1292.58 ; v1(8115.6,2585.15) 8115.82,2585.37 8147.68,2585.37 RT4_A3.2@8147.91,2585.59 ; v1(8162.37,626.09) 8165.05,623.41 8176.04,623.41 8203.41,596.03 C148_A3.2@8203.41,595.05 ; C46_A3.1@8214.29,1164.63 8217.44,1164.63 8228.82,1176 8228.82,1246.08 8230.1,1247.37 8230.1,1248.35 8244.8,1263.05 C64_A3.1@8245.79,1263.05 ; D12_A3.3@8340.43,626.94 8342.85,624.52 v1@8389.55,624.52
  Bottom Layer w8: C160.1@6903.54,639.76 6960.21,639.76 6968.65,648.2 v1(7123.51,648.2) 7124.58,648.2 v1@7125.98,649.61 ; RT2_A3.2@7157.58,2584.37 v1(7202.65,2584.37) ; C137_A3.2@7290.94,3649.17 7290.94,3676.92 7296.59,3682.57 7298.46,3682.57 7303.15,3687.26 v1(7303.15,3750) ; C127_A3.2@7353.43,3649.17 7353.43,3653.11 7369.91,3669.59 7369.91,3677.09 7370.11,3677.28 7370.11,3681.22 7378.42,3689.53 7378.42,3730.86 7363.59,3745.69 7362.54,3745.69 7354.73,3753.5 C131_A3.2@7354.73,3757.44 C122_A3.2@7411.43,3757.44 ; C117_A3.2@7415.93,3649.17 7417.43,3650.67 7417.43,3676.92 7423.08,3682.57 7434.16,3682.57 7441.11,3689.53 7441.11,3730.86 7426.28,3745.69 7425.24,3745.69 7417.43,3753.5 C122_A3.2@7417.43,3757.44 C122_A3.2@7411.43,3757.44 ; C122_A3.2@7417.05,3763.05 C122_A3.2@7411.43,3757.44 ; v1(7420.61,2583.51) v1@7421.23,2584.13 ; C109_A3.2@7478.42,3649.17 7478.42,3645.24 7486.23,3637.42 7490.17,3637.42 7518.81,3608.78 7530.13,3608.78 R140_A3.1@7537.94,3600.97 ; v1(7519.68,3740.16) 7517,3737.48 7517,3717.47 7509.83,3710.29 7509.83,3694.07 7538.4,3665.5 7538.4,3630.09 7537.94,3629.64 R140_A3.1@7537.94,3600.97 ; v1(7539.37,3562.99) 7539.37,3599.54 R140_A3.1@7537.94,3600.97 ; RT3_A3.2@7854.5,2583.97 7854.98,2584.45 7886.98,2584.45 v1@7889.49,2581.95 ; C110_A3.2@8263.5,1174.47 8256.95,1181.02 8256.95,1196.25 8251.82,1201.38 v1(8251.82,1205.17) 8251.82,1208.96 8256.95,1214.09 8256.95,1230.76 8259.71,1233.52 C114_A3.2@8273.34,1233.52 ; R136_A3.1@8268.83,921.01 8268.83,920.02 8299.35,889.51 Q1_A3.2@8327.54,889.51 ; v1(8389.55,622.09) 8578.69,622.09 C161.1@8580.71,620.08 ; R137_A3.1@8452.61,921.01 8452.61,920.02 R137_A3.1@8467.31,905.32 ; v1@8489.88,889.04 8491.05,890.21 8505.3,890.21 8508.78,886.73 Q2_A3.2@8508.78,884.82
  Bottom Layer w25: C129_A3.2@8271.76,1381.16 C124_A3.2@8271.76,1426.11 C119_A3.2@8271.76,1478.01 ; C129_A3.2@8273.34,1381.16 8273.34,1311.83 v1(8295.52,1289.66) ; D10_A3.2@8419.32,1747.22 8419.32,1735.96 8449.32,1705.96 C191_A3.1@8614.77,1705.96 ; C191_A3.1@8614.77,1706.46 8619.98,1701.25 8652.08,1701.25 v1@8657.2,1696.12
  other v1: 7337.57,619.13 7927.31,749.61 7658.72,787.84 8344.36,810.29 8165.05,834.97 8389.62,850.84 8128.09,881.74 8181.88,881.74 8488.04,890.21 7966.68,916.93 7943.82,948.88 8047.95,960.03 8181.51,966.34 6763.82,976.8 6818.93,976.8 6874.04,976.8 6929.15,976.8 6984.26,976.8 7039.37,976.8 7094.48,976.8 7149.59,976.8 7227.34,976.8 7282.46,976.8 7337.57,976.8 7943.82,981.79 8040.66,995.41 8617.49,1021.47 8265.7,1097.28 8509.04,1122.85 7101.57,1461.56 8089.97,1501.76 7139.59,1666.96 8660.77,1696.18 8660.77,1738.67 6929.13,1751.97 8661.5,1781.64 8660.77,1824.85 7234.25,3533.46 6880.72,3724.72 7237.44,3759.84 7687.8,3832.99 7728.9,3832.99 7770,3832.99 7811.11,3832.99 7852.21,3832.99 7892.63,3832.99 7933.73,3832.99 7974.83,3832.99 8015.93,3832.99 8057.03,3832.99 8095.27,3832.64 8136.37,3832.64 8177.47,3832.64 8218.57,3832.64 8259.67,3832.64 8296.77,3832.64 8541.72,3841.79 8586.68,3841.79 8533.46,3868.11 8563.71,3876.29
  other v2: 7713.13,1182.21 7764.31,1182.21 7815.49,1182.21 7866.67,1182.21 7917.85,1182.21 7969.03,1182.21 7713.13,1233.39 7764.31,1233.39 7815.49,1233.39 7866.67,1233.39 7917.85,1233.39 7969.03,1233.39 7713.13,1284.57 7764.31,1284.57 7815.49,1284.57 7866.67,1284.57 7917.85,1284.57 7969.03,1284.57 7713.13,1335.75 7764.31,1335.75 7815.49,1335.75 7866.67,1335.75 7917.85,1335.75 7969.03,1335.75 7713.13,1386.94 7764.31,1386.94 7815.49,1386.94 7866.67,1386.94 7917.85,1386.94 7969.03,1386.94 7713.13,1438.12 7764.31,1438.12 7815.49,1438.12 7866.67,1438.12 7917.85,1438.12 7969.03,1438.12
GND_A4: C6_A4.2 C9_A4.2 C12_A4.2 C18_A4.1 C20_A4.2 C24_A4.2 C26_A4.1 C28_A4.2 C32_A4.2 C38_A4.1 C40_A4.2 C43_A4.2 C46_A4.1 C48_A4.2 C51_A4.2 C55_A4.1 C57_A4.2 C60_A4.2 C64_A4.1 C66_A4.2 C70_A4.2 C78_A4.2 C83_A4.2 C87_A4.2 C92_A4.2 C100_A4.2 C103_A4.2 C107_A4.2 C108_A4.2 C109_A4.2 C110_A4.2 C111_A4.2 C112_A4.2 C113_A4.2 C114_A4.2 C115_A4.1 C116_A4.2 C117_A4.2 C118_A4.2 C119_A4.2 C120_A4.2 C121_A4.2 C122_A4.2 C123_A4.2 C124_A4.2 C125_A4.1 C126_A4.2 C127_A4.2 C128_A4.2 C129_A4.2 C130_A4.2 C131_A4.2 C132_A4.2 C133_A4.2 C135_A4.1 C136_A4.2 C137_A4.2 C138_A4.2 C140_A4.2 C147_A4.1 C148_A4.2 C149_A4.2 C150_A4.2 C151_A4.2 C152_A4.2 C162.1 C166.1 C191_A4.1 D4_A4.2 D6_A4.2 D7_A4.2 D8_A4.2 D9_A4.2 D10_A4.2 D11_A4.3 D12_A4.3 J1_A4.4 J1_A4.6 J1_A4.10 J2_A4.21 J2_A4.25 Q1_A4.2 Q2_A4.2 R136_A4.1 R137_A4.1 R140_A4.1 R148_A4.1 R151_A4.1 RT1_A4.2 RT2_A4.2 RT3_A4.2 RT4_A4.2 U1_A4.42 U1_A4.55 U1_A4.65 U2_A4.6 U2_A4.8 U3_A4.6 U3_A4.8 | length 9682.3
  Top Layer w8: v1@2477.29,68.9 2478.52,67.67 2525.89,67.67 D12_A4.3@2528.32,65.24 2540.09,65.24 D12_A4.3@2547.9,73.05 ; C148_A4.2@2665.33,97.14 2665.33,96.15 2692.71,68.78 2703.69,68.78 v1(2706.37,66.1) ; J1_A4.4@8858.57,3974.78 v1(8858.57,4060.48) ; J1_A4.6@8905.81,3981.48 8911.04,3986.71 v1(8911.04,4061.75) ; J1_A4.6@8909.47,3972.94 J1_A4.6@8909.79,3972.62 ; v1(9005.13,4060.32) 9005.13,3977.28 J1_A4.10@9006.25,3976.17 ; v1(9259.49,1448.63) 9258.59,1449.53 9258.59,1464.2 9250.44,1472.36 9250.44,1505.37 9198.1,1557.71 9124.02,1631.79 9124.02,3297.24 9293.49,3466.72 9448.9,3466.72 9552.34,3570.16 J2_A4.25@9552.34,3647.12 ; v1(9443.74,644.99) 9446.31,647.56 9489.17,647.56 D11_A4.3@9491.21,649.61 ; C147_A4.1@9613.19,618.63 9615.9,615.92 9654.38,615.92 v1@9658.54,620.08 ; v1(9740.84,2580.3) RT1_A4.2@9777.49,2580.3 ; v1(9858.17,3554.93) 9832.73,3554.93 9655.98,3378.17 9619.08,3378.17 9585.66,3344.76 9383.83,3344.76 9258.88,3219.8 9258.88,1958.51 9274.44,1942.95 9275.19,1942.95 9293.1,1925.04 9294.54,1925.04 9298.27,1921.32 9511.94,1921.32 9532.72,1900.53 v1(9532.72,1848.75) 9532.72,1727.13 9519.48,1713.89 9519.48,1178.7 9668.38,1029.8 9668.38,1013.78 9697.91,984.25 9713.92,984.25 9866.42,831.76 10027.17,831.76 10067.24,871.83 10067.24,883.8 C107_A4.2@10071.95,888.51 ; v1(10090.12,764.43) 10090.12,826.77 10116.11,852.76 10116.11,878.53 10127.06,889.48 10127.06,890.37 10173.2,936.51 C38_A4.1@10174.18,936.51 10175.17,936.51 10189.87,951.21 10189.87,992.2 v1(10190.84,993.17) U1_A4.42@10190.84,1082.55 ; v1@10211.97,2581.77 v1(10212.02,2581.72) ; U1_A4.55@10385.72,1277.43 10436.24,1277.43 10437.65,1276.02 10464.02,1276.02 10478.42,1290.42 10534.46,1290.42 10564.05,1260.83 C64_A4.1@10564.05,1259.84 ; v1@10406.57,1496.06 10408.71,1496.06 10426.97,1514.32 10431.04,1514.32 10444.12,1527.4 C26_A4.1@10444.12,1558.6 10562.29,1558.6 D9_A4.2@10583.37,1537.51 10583.38,1368.46 10591.19,1360.65 C135_A4.1@10591.99,1360.65 10591.99,1310.21 10612.83,1289.37 v1@10613.26,1289.37 ; v1(10435.83,2581.94) 10436.05,2582.16 10467.91,2582.16 RT4_A4.2@10468.14,2582.39 ; C46_A4.1@10534.52,1161.42 10537.67,1161.42 10549.05,1172.79 10549.05,1242.87 10550.33,1244.16 10550.33,1245.14 10565.03,1259.84 C64_A4.1@10566.02,1259.84
  Bottom Layer w8: C166.1@2281.43,72.99 2284.32,70.09 2479.12,70.09 v1@2480.32,68.9 ; RT2_A4.2@9477.81,2581.17 v1(9522.88,2581.17) ; C137_A4.2@9611.17,3645.96 9611.17,3673.71 9616.82,3679.37 9628.99,3679.37 9635.95,3686.32 9635.95,3720.8 v1(9616.59,3740.16) ; C127_A4.2@9673.66,3645.96 9673.66,3649.9 9690.14,3666.38 9690.14,3673.88 9690.34,3674.08 9690.34,3678.01 9698.65,3686.32 9698.65,3727.65 9683.82,3742.48 9682.77,3742.48 9674.96,3750.29 C131_A4.2@9674.96,3754.23 C122_A4.2@9731.66,3754.23 ; C117_A4.2@9736.16,3645.96 9737.66,3647.47 9737.66,3673.71 9743.31,3679.37 9754.39,3679.37 9761.34,3686.32 9761.34,3727.65 9746.51,3742.48 9745.47,3742.48 9737.66,3750.29 C122_A4.2@9737.66,3754.23 C122_A4.2@9731.66,3754.23 ; C122_A4.2@9737.28,3759.84 C122_A4.2@9731.66,3754.23 ; v1(9740.84,2580.3) v1@9741.46,2580.92 ; C109_A4.2@9798.65,3649.9 C109_A4.2@9798.65,3645.96 9798.65,3642.03 9806.46,3634.22 9810.4,3634.22 9839.04,3605.58 9850.36,3605.58 R140_A4.1@9858.17,3597.76 ; v1(9842.52,3740.16) 9839.84,3737.48 9839.84,3720.52 9832.47,3713.15 9832.47,3688.45 9858.63,3662.29 9858.63,3626.88 9858.17,3626.43 R140_A4.1@9858.17,3597.76 ; v1(9858.17,3554.93) R140_A4.1@9858.17,3597.76 ; RT3_A4.2@10174.73,2580.76 10175.21,2581.24 10207.21,2581.24 v1@10209.72,2578.74 ; C110_A4.2@10583.73,1171.26 10577.18,1177.81 10577.18,1193.04 10572.05,1198.17 v1(10572.05,1201.96) 10572.05,1205.75 10577.18,1210.88 10577.18,1227.55 10579.94,1230.32 C114_A4.2@10593.57,1230.32 ; R136_A4.1@10589.06,917.8 10589.06,916.81 10619.58,886.3 Q1_A4.2@10647.77,886.3 ; R137_A4.1@10772.84,917.8 10772.84,916.81 R137_A4.1@10787.54,902.11 ; v1@10810.11,885.83 10811.28,887 10825.53,887 10829.01,883.52 Q2_A4.2@10829.01,881.62
  Bottom Layer w25: C129_A4.2@10591.99,1377.95 C124_A4.2@10591.99,1422.9 C119_A4.2@10591.99,1474.8 ; C129_A4.2@10593.57,1377.95 10593.57,1308.62 v1(10615.75,1286.45) ; D10_A4.2@10739.55,1744.01 10739.55,1732.76 10769.55,1702.76 C191_A4.1@10935,1702.76 ; C191_A4.1@10935,1703.26 10940.21,1698.04 10972.31,1698.04 v1@10977.43,1692.91
  other v1: 2892.35,18.37 2925.54,18.37 2958.72,18.37 3000.62,18.37 3033.81,18.37 3066.99,18.37 3100.17,18.37 3133.36,18.37 3166.54,18.37 3199.73,18.37 3236.84,18.37 3270.03,18.37 3303.21,18.37 3336.4,18.37 3369.58,18.37 3402.76,18.37 3435.95,18.37 3473.06,18.37 3506.25,18.37 3539.43,18.37 3572.62,18.37 3605.8,18.37 3638.98,18.37 3672.17,18.37 3709.28,18.37 3742.47,18.37 3775.65,18.37 3808.84,18.37 3842.02,18.37 3875.21,18.37 3908.39,18.37 3945.5,18.37 3978.69,18.37 4011.87,18.37 4045.06,18.37 4078.24,18.37 4111.43,18.37 4144.61,18.37 4181.72,18.37 4214.91,18.37 4248.09,18.37 4281.28,18.37 4314.46,18.37 4347.65,18.37 4380.83,18.37 4417.94,18.37 4451.13,18.37 4484.31,18.37 4517.5,18.37 4550.68,18.37 4583.87,18.37 4617.05,18.37 4654.16,18.37 4687.35,18.37 4720.53,18.37 4753.72,18.37 4786.9,18.37 4820.09,18.37 4853.27,18.37 4900.23,18.37 4933.41,18.37 4966.6,18.37 4999.78,18.37 5032.97,18.37 5066.15,18.37 5099.34,18.37 5136.45,18.37 5169.63,18.37 5202.82,18.37 5236,18.37 5269.19,18.37 5302.37,18.37 5335.56,18.37 5372.67,18.37 5405.85,18.37 5439.04,18.37 5472.22,18.37 5505.41,18.37 5538.59,18.37 5571.78,18.37 5608.89,18.37 5642.07,18.37 5675.26,18.37 5708.44,18.37 5741.63,18.37 5774.81,18.37 5808,18.37 5845.11,18.37 5878.29,18.37 5911.48,18.37 5944.66,18.37 5977.85,18.37 6011.03,18.37 6044.22,18.37 6081.33,18.37 6114.51,18.37 6147.7,18.37 6180.88,18.37 6214.07,18.37 6247.25,18.37 6280.44,18.37 6317.55,18.37 6350.73,18.37 6383.92,18.37 6417.1,18.37 6450.29,18.37 6483.47,18.37 6516.66,18.37 6553.77,18.37 6586.95,18.37 6620.14,18.37 6653.32,18.37 6686.51,18.37 6719.69,18.37 6752.88,18.37 6789.99,18.37 6823.18,18.37 6856.36,18.37 6889.54,18.37 6922.73,18.37 6955.91,18.37 6989.1,18.37 7026.21,18.37 7059.4,18.37 7092.58,18.37 7125.77,18.37 7158.95,18.37 7192.13,18.37 7225.32,18.37 7262.43,18.37 7295.62,18.37 7328.8,18.37 7361.99,18.37 7395.17,18.37 7428.35,18.37 7461.54,18.37 7498.65,18.37 7531.84,18.37 7565.02,18.37 7598.21,18.37 7631.39,18.37 7664.58,18.37 7697.76,18.37 7734.87,18.37 7768.06,18.37 7801.24,18.37 7834.43,18.37 7867.61,18.37 7900.8,18.37 7933.98,18.37 7971.09,18.37 8004.28,18.37 8037.46,18.37 8070.65,18.37 8103.83,18.37 8137.02,18.37 8170.2,18.37 8207.31,18.37 8240.5,18.37 8273.68,18.37 8306.87,18.37 8340.05,18.37 8373.24,18.37 8406.42,18.37 8443.53,18.37 8476.72,18.37 8509.9,18.37 8543.09,18.37 8576.27,18.37 8609.46,18.37 8642.64,18.37 8684.54,18.37 8717.73,18.37 8750.91,18.37 8788.02,18.37 8821.21,18.37 8854.39,18.37 8887.58,18.37 8920.76,18.37 8953.95,18.37 8987.13,18.37 9024.24,18.37 9057.43,18.37 9090.61,18.37 9123.8,18.37 9156.98,18.37 9190.17,18.37 9223.35,18.37 9260.46,18.37 9293.65,18.37 9326.83,18.37 9360.02,18.37 9393.2,18.37 9426.39,18.37 9459.57,18.37 9497.81,18.37 9531,18.37 9564.18,18.37 9597.37,18.37 9634.48,18.37 9667.66,18.37 9700.85,18.37 9734.03,18.37 9767.22,18.37 9800.4,18.37 9833.59,18.37 9881.67,18.37 9914.86,18.37 9948.04,18.37 9981.22,18.37 10018.34,18.37 10051.52,18.37 10084.71,18.37 10117.89,18.37 10151.08,18.37 10184.26,18.37 10217.45,18.37 10269.19,18.37 10302.37,18.37 10335.56,18.37 10365.08,38.06 10394.61,67.59 2479.2,70.09 10414.3,97.11 2882.51,126.64 2915.7,126.64 2948.88,126.64 2982.06,126.64 3015.25,126.64 3048.43,126.64 3081.62,126.64 3118.73,126.64 3151.92,126.64 3185.1,126.64 3218.28,126.64 3251.47,126.64 3284.65,126.64 3317.84,126.64 3354.95,126.64 3388.14,126.64 3421.32,126.64 3454.51,126.64 3487.69,126.64 3520.87,126.64 3554.06,126.64 3591.17,126.64 3624.36,126.64 3657.54,126.64 3690.73,126.64 3723.91,126.64 3757.1,126.64 3790.28,126.64 3827.39,126.64 3860.58,126.64 3893.76,126.64 3926.95,126.64 3960.13,126.64 3993.32,126.64 4026.5,126.64 4063.61,126.64 4096.8,126.64 4129.98,126.64 4163.17,126.64 4196.35,126.64 4229.54,126.64 4262.72,126.64 4299.83,126.64 4333.02,126.64 4366.2,126.64 4399.39,126.64 4432.57,126.64 4465.76,126.64 4498.94,126.64 4536.05,126.64 4569.24,126.64 4602.42,126.64 4635.61,126.64 4668.79,126.64 4701.98,126.64 4735.16,126.64 4782.12,126.64 4815.3,126.64 4848.49,126.64 4881.67,126.64 4914.86,126.64 4948.04,126.64 4981.22,126.64 5018.34,126.64 5051.52,126.64 5084.71,126.64 5117.89,126.64 5151.08,126.64 5184.26,126.64 5217.45,126.64 5254.56,126.64 5287.74,126.64 5320.93,126.64 5354.11,126.64 5387.3,126.64 5420.48,126.64 5453.67,126.64 5490.78,126.64 5523.96,126.64 5557.15,126.64 5590.33,126.64 5623.52,126.64 5656.7,126.64 5689.89,126.64 5727,126.64 5760.18,126.64 5793.37,126.64 5826.55,126.64 5859.74,126.64 5892.92,126.64 5926.11,126.64 5963.22,126.64 5996.4,126.64 6029.59,126.64 6062.77,126.64 6095.96,126.64 6129.14,126.64 6162.33,126.64 6199.44,126.64 6232.62,126.64 6265.81,126.64 6298.99,126.64 6332.18,126.64 6365.36,126.64 6398.55,126.64 6435.66,126.64 6468.84,126.64 6502.03,126.64 6535.21,126.64 6568.4,126.64 6601.58,126.64 6634.77,126.64 6671.88,126.64 6705.07,126.64 6738.25,126.64 6771.43,126.64 6804.62,126.64 6837.8,126.64 6870.99,126.64 6908.1,126.64 6941.29,126.64 6974.47,126.64 7007.65,126.64 7040.84,126.64 7074.02,126.64 7107.21,126.64 7144.32,126.64 7177.51,126.64 7210.69,126.64 7243.88,126.64 7277.06,126.64 7310.24,126.64 7343.43,126.64 7380.54,126.64 7413.73,126.64 7446.91,126.64 7480.1,126.64 7513.28,126.64 7546.47,126.64 7579.65,126.64 7616.76,126.64 7649.95,126.64 7683.13,126.64 7716.32,126.64 7749.5,126.64 7782.69,126.64 7815.87,126.64 7852.98,126.64 7886.17,126.64 7919.35,126.64 7952.54,126.64 7985.72,126.64 8018.91,126.64 8052.09,126.64 8089.2,126.64 8122.39,126.64 8155.57,126.64 8188.76,126.64 8221.94,126.64 8255.13,126.64 8288.31,126.64 8325.42,126.64 8358.61,126.64 8391.79,126.64 8424.98,126.64 8458.16,126.64 8491.35,126.64 8524.53,126.64 8566.43,126.64 8599.61,126.64 8632.8,126.64 8669.91,126.64 8703.1,126.64 8736.28,126.64 8769.47,126.64 8802.65,126.64 8835.84,126.64 8869.02,126.64 8906.13,126.64 8939.32,126.64 8972.5,126.64 9005.69,126.64 9038.87,126.64 9072.06,126.64 9105.24,126.64 9142.35,126.64 9175.54,126.64 9208.72,126.64 9241.91,126.64 9275.09,126.64 9308.28,126.64 9341.46,126.64 9379.7,126.64 9412.89,126.64 9446.07,126.64 9479.26,126.64 9516.37,126.64 9549.55,126.64 9582.74,126.64 9615.92,126.64 9649.11,126.64 9682.29,126.64 9715.48,126.64 9763.56,126.64 9796.75,126.64 9829.93,126.64 9863.11,126.64 9900.23,126.64 9933.41,126.64 9966.6,126.64 9999.78,126.64 10032.97,126.64 10066.15,126.64 10099.33,126.64 10151.08,126.64 10184.26,126.64 10217.45,126.64 10414.7,133.92 10246.97,146.33 10414.7,167.1 10276.5,175.85 10414.7,200.29 10296.19,205.38 10414.7,233.47 10296.59,242.19 10414.7,266.66 10296.59,275.37 10414.7,306.03 10296.59,308.56 10296.59,341.74 10414.7,344.27 10296.59,374.93 10414.7,377.45 10414.7,410.64 10296.59,413.17 10414.7,443.82 10296.59,446.35 10296.59,482.06 10414.7,482.06 10296.59,515.25 10414.7,515.25 10296.59,548.43 10414.7,548.43 10296.59,581.62 10414.7,581.62 10267.06,607.49 10444.23,607.49 9657.8,615.92 10444.23,637.02 10267.06,646.86 10444.23,676.39 10267.06,680.04 10444.23,709.57 10247.54,746.4 9978.95,784.63 10664.59,807.09 10485.28,831.76 10709.85,847.63 10448.32,878.53 10502.11,878.53 10808.27,887 10286.91,913.72 10264.05,945.68 10368.18,956.82 10501.74,963.13 9084.05,973.59 9139.16,973.59 9194.27,973.59 9249.38,973.59 9304.49,973.59 9359.6,973.59 9414.71,973.59 9469.82,973.59 9547.57,973.59 9602.69,973.59 9657.8,973.59 10264.05,978.59 10360.89,992.2 10937.72,1018.27 10585.93,1094.07 10829.27,1119.64 9421.8,1458.36 10410.2,1498.55 9459.82,1663.75 10981,1692.97 10981,1735.46 9242.13,1761.81 10981.73,1778.44 10981,1821.64 9340.55,1889.76 9202.76,3720.47 9559.78,3750 10578.82,3828.35 10415.5,3829.44 10456.6,3829.44 10497.7,3829.44 10538.8,3829.44 10610.24,3828.74 10008.03,3829.78 10049.13,3829.78 10090.23,3829.78 10131.34,3829.78 10172.44,3829.78 10212.86,3829.78 10253.96,3829.78 10295.06,3829.78 10336.16,3829.78 10377.26,3829.78 10861.95,3838.58 10906.91,3838.58 10856.3,3868.11 10883.94,3873.08
  other v2: 10033.36,1179 10084.54,1179 10135.72,1179 10186.9,1179 10238.08,1179 10289.26,1179 10033.36,1230.18 10084.54,1230.18 10135.72,1230.18 10186.9,1230.18 10238.08,1230.18 10289.26,1230.18 10033.36,1281.37 10084.54,1281.37 10135.72,1281.37 10186.9,1281.37 10238.08,1281.37 10289.26,1281.37 10033.36,1332.55 10084.54,1332.55 10135.72,1332.55 10186.9,1332.55 10238.08,1332.55 10289.26,1332.55 10033.36,1383.73 10084.54,1383.73 10135.72,1383.73 10186.9,1383.73 10238.08,1383.73 10289.26,1383.73 10033.36,1434.91 10084.54,1434.91 10135.72,1434.91 10186.9,1434.91 10238.08,1434.91 10289.26,1434.91
GND_Stage1: C187.1 C189.2 C190.1 U9.12 U9.13 U9.14 U9.15 U9.16 U10.4 U10.5 U10.6 U10.7 U10.8 | length 50.3
  Top Layer w8: C189.2@1484.28,1562.56 C189.2@1505.28,1583.56 ; C189.2@1490.96,1583.03 C189.2@1497.31,1576.68 ; C189.2@1497.85,1576.13 C189.2@1505.28,1583.56 ; C189.2@1505.28,1584.65 C189.2@1505.28,1583.56
  other v1: 1525.59,1302.99 1488.41,1304.8 1574.8,1304.8 1604.33,1304.8 1525.59,1330.63 1525.59,1358.27 1427.17,1555.12 1456.69,1555.12 1427.17,1584.65 1456.69,1584.65 1427.17,1614.17 1456.69,1614.17
GND_Stage2: C211.1 C212.2 C217.1 R211.2 U10.12 U10.13 U10.14 U10.15 U10.16 U50.2 U50.8 | length 373.7
  Top Layer w8: U50.2@1777.69,957.68 U50.2@1794.18,957.68 ; U50.8@1777.69,1257.68 1907.82,1257.68 1925.34,1240.16 v1(1929.13,1240.16) ; 2053.92,1388.63 2054.28,1388.63 2054.28,1381.76 C211.1@2057.3,1378.74
  Top Layer w20: U50.2@1811.02,954.72 1820.87,944.88 1909.19,944.88 1920.17,933.9 C217.1@1937.17,933.9 ; C217.1@1948.82,925.2 1956.54,932.91 1956.54,971.86 1957.84,973.16 v1(1957.84,973.71)
  other v1: 2033.98,1504.01 2056.98,1503.56 2056.98,1529.42 2033.98,1529.87 2056.98,1556.16 2033.98,1556.61
GPIO3_A1: C119_A1.1 R153_A1.1 U1_A1.64 | length 1677.6
  Top Layer w8: v1(2509.84,1397.64) 2507.82,1395.62 2507.82,1348.89 R153_A1.1@2536.11,1320.6 ; U1_A1.64@3433.88,1454.59 3457.5,1454.59 3492.28,1489.38 v1@3495.29,1489.38
  Signal Layer 2 w8: v1@2500,1397.64 v1(2509.84,1397.64) 2595.94,1483.74 2595.94,1489.87 2679.36,1573.29 2846,1573.29 3019.42,1746.7 3500.57,1746.7 3507.56,1739.71 3507.56,1597.95 3499.16,1589.55 v1(3499.16,1489.38)
  Bottom Layer w8: v1(3499.16,1489.38) 3539.76,1489.38 3549.34,1479.8 3558.46,1479.8 3563.45,1474.8 C119_A1.1@3592.9,1474.8
GPIO3_A2: C119_A2.1 R153_A2.1 U1_A2.64 | length 1675.4
  Top Layer w8: v1(4799.53,1398.43) 4799.53,1352.2 R153_A2.1@4831.12,1320.6 ; U1_A2.64@5728.89,1454.59 5752.51,1454.59 5787.3,1489.38 v1@5790.3,1489.38
  Signal Layer 2 w8: v1@4795.02,1397.64 4798.73,1397.64 v1(4799.53,1398.43) 4974.38,1573.29 5141.02,1573.29 5314.43,1746.7 5795.59,1746.7 5802.58,1739.71 5802.58,1597.95 5794.18,1589.55 v1(5794.18,1489.38)
  Bottom Layer w8: v1(5794.18,1489.38) 5834.77,1489.38 5844.35,1479.8 5853.47,1479.8 5858.47,1474.8 C119_A2.1@5887.92,1474.8
GPIO3_A3: C119_A3.1 R153_A3.1 U1_A3.64 | length 1675.4
  Top Layer w8: v1(7136.12,1401.64) 7136.12,1355.41 R153_A3.1@7167.72,1323.81 ; U1_A3.64@8065.49,1457.8 8089.11,1457.8 8123.89,1492.59 v1@8126.9,1492.59
  Signal Layer 2 w8: v1@7131.61,1400.85 7135.33,1400.85 v1(7136.12,1401.64) 7310.98,1576.5 7477.62,1576.5 7651.03,1749.91 8132.19,1749.91 8139.17,1742.92 8139.17,1601.16 8130.77,1592.76 v1(8130.77,1492.59)
  Bottom Layer w8: v1(8130.77,1492.59) 8171.37,1492.59 8180.95,1483.01 8190.07,1483.01 8195.07,1478.01 C119_A3.1@8224.52,1478.01
GPIO3_A4: C119_A4.1 R153_A4.1 U1_A4.64 | length 1668.6
  Top Layer w8: v1(9458.64,1397.64) 9458.64,1349.91 R153_A4.1@9487.95,1320.6 ; U1_A4.64@10385.72,1454.59 10409.34,1454.59 10444.12,1489.38 v1@10447.13,1489.38
  Signal Layer 2 w8: v1(9458.64,1397.64) 9458.64,1400.72 9631.21,1573.29 9797.84,1573.29 9971.26,1746.7 10452.42,1746.7 10459.4,1739.71 10459.4,1597.95 10451,1589.55 v1(10451,1489.38)
  Bottom Layer w8: v1(10451,1489.38) 10491.6,1489.38 10501.18,1479.8 10510.3,1479.8 10515.3,1474.8 C119_A4.1@10544.75,1474.8
GPIO4_A1: C124_A1.1 R157_A1.1 U1_A1.63 | length 1774.8
  Top Layer w8: v1(2474.77,1395.54) 2474.77,1326.93 R157_A1.1@2481.1,1320.6 ; U1_A1.63@3433.88,1434.91 3435.78,1436.81 3467.18,1436.81 3475.28,1444.91 3475.28,1449.65 3489.56,1463.92 v1(3527.32,1463.92)
  Signal Layer 2 w8: v1(2474.77,1395.54) 2476.62,1397.39 2476.62,1410.22 2651.05,1584.65 2664.56,1584.65 2669.08,1589.16 2835.04,1589.16 3008.46,1762.58 3519.89,1762.58 3527.32,1755.14 v1(3527.32,1463.92)
  Bottom Layer w8: v1(3527.32,1463.92) 3529.7,1461.54 3550.32,1461.54 3588.97,1422.9 C124_A1.1@3592.9,1422.9
GPIO4_A2: C124_A2.1 R157_A2.1 U1_A2.63 | length 1779.7
  Top Layer w8: v1(4763.77,1397.64) 4763.77,1393.84 4776.11,1381.5 R157_A2.1@4776.11,1320.6 ; U1_A2.63@5728.89,1434.91 5730.8,1436.81 5762.2,1436.81 5770.29,1444.91 5770.29,1449.65 5784.57,1463.92 v1(5822.34,1463.92)
  Signal Layer 2 w8: v1(4763.77,1397.64) 4763.77,1401.43 4771.64,1409.29 4771.64,1410.22 4946.07,1584.65 4959.57,1584.65 4964.09,1589.16 5130.06,1589.16 5303.47,1762.58 5814.9,1762.58 5822.34,1755.14 v1(5822.34,1463.92)
  Bottom Layer w8: v1(5822.34,1463.92) 5824.72,1461.54 5845.34,1461.54 5883.98,1422.9 C124_A2.1@5887.92,1422.9
GPIO4_A3: C124_A3.1 R157_A3.1 U1_A3.63 | length 1773.2
  Top Layer w8: v1(7109.48,1386.03) 7111.09,1384.41 7111.09,1325.43 R157_A3.1@7112.71,1323.81 ; U1_A3.63@8065.49,1438.12 8067.4,1440.02 8098.79,1440.02 8106.89,1448.12 8106.89,1452.86 8121.17,1467.13 v1(8158.93,1467.13)
  Signal Layer 2 w8: v1(7109.48,1386.03) 7108.23,1387.27 7108.23,1413.43 7282.66,1587.85 7296.17,1587.85 7300.69,1592.37 7466.66,1592.37 7640.07,1765.78 8151.5,1765.78 8158.93,1758.35 v1(8158.93,1467.13)
  Bottom Layer w8: v1(8158.93,1467.13) 8161.31,1464.75 8181.94,1464.75 8220.58,1426.11 C124_A3.1@8224.52,1426.11
GPIO4_A4: C124_A4.1 R157_A4.1 U1_A4.63 | length 1774.8
  Top Layer w8: v1(9426.61,1395.54) 9426.61,1326.93 R157_A4.1@9432.94,1320.6 ; U1_A4.63@10385.72,1434.91 10387.62,1436.81 10419.02,1436.81 10427.12,1444.91 10427.12,1449.65 10441.4,1463.92 v1(10479.16,1463.92)
  Signal Layer 2 w8: v1(9426.61,1395.54) 9428.46,1397.39 9428.46,1410.22 9602.89,1584.65 9616.4,1584.65 9620.92,1589.16 9786.89,1589.16 9960.3,1762.58 10471.73,1762.58 10479.16,1755.14 v1(10479.16,1463.92)
  Bottom Layer w8: v1(10479.16,1463.92) 10481.54,1461.54 10502.17,1461.54 10540.81,1422.9 C124_A4.1@10544.75,1422.9
GPIO5_A1: C129_A1.1 R159_A1.1 U1_A1.62 | length 1952.3
  Top Layer w8: R159_A1.1@2426.09,1320.6 2426.09,1324.54 2449.6,1348.05 v1(2449.6,1429.09) ; U1_A1.62@3433.88,1415.22 3435.78,1417.13 3467.18,1417.13 3470.99,1420.94 3474.68,1420.94 3483.11,1429.37 3483.56,1429.37 3493.72,1439.53 v1@3497.51,1439.53
  Signal Layer 2 w8: v1(2449.6,1429.09) 2471.4,1429.09 2473.25,1430.94 2474.9,1430.94 2494.81,1450.86 2494.81,1478.64 2616.69,1600.52 2657.98,1600.52 2662.5,1605.04 2828.47,1605.04 3001.88,1778.45 3526.46,1778.45 3550.2,1754.71 3550.2,1454.45 3535.28,1439.53 v1(3499.16,1439.53)
  Bottom Layer w8: v1(3499.16,1439.53) 3533.44,1439.53 3558.99,1413.98 3558.99,1399.22 3588.97,1369.24 C129_A1.1@3592.9,1369.24
GPIO5_A2: C129_A2.1 R159_A2.1 U1_A2.62 | length 1955.4
  Top Layer w8: R159_A2.1@4721.11,1320.6 4721.11,1324.54 4744.62,1348.05 4744.62,1375.72 4740.89,1379.44 4740.89,1407.11 4741.94,1408.16 4741.94,1426.41 v1(4744.62,1429.09) ; U1_A2.62@5728.89,1415.22 5730.8,1417.13 5762.2,1417.13 5766.01,1420.94 5769.7,1420.94 5778.12,1429.37 5778.58,1429.37 5788.74,1439.53 v1@5792.53,1439.53
  Signal Layer 2 w8: v1(4744.62,1429.09) 4766.42,1429.09 4768.27,1430.94 4769.91,1430.94 4789.83,1450.86 4789.83,1478.64 4911.71,1600.52 4953,1600.52 4957.52,1605.04 5123.48,1605.04 5296.9,1778.45 5821.48,1778.45 5845.21,1754.71 5845.21,1454.45 5830.3,1439.53 v1(5794.18,1439.53)
  Bottom Layer w8: v1(5794.18,1439.53) 5828.46,1439.53 5854.01,1413.98 5854.01,1399.22 5883.98,1369.24 C129_A2.1@5887.92,1369.24
GPIO5_A3: C129_A3.1 R159_A3.1 U1_A3.62 | length 1946.2
  Top Layer w8: R159_A3.1@7057.7,1323.81 7057.7,1327.75 7086.6,1356.65 v1(7086.6,1427.16) ; U1_A3.62@8065.49,1418.43 8067.4,1420.34 8098.79,1420.34 8102.6,1424.15 8106.29,1424.15 8114.72,1432.57 8115.17,1432.57 8125.34,1442.74 v1@8129.13,1442.74
  Signal Layer 2 w8: v1(7086.6,1427.16) 7090.39,1427.16 7101.91,1438.69 7111.05,1438.69 7126.43,1454.07 7126.43,1481.85 7248.31,1603.73 7289.6,1603.73 7294.11,1608.25 7460.08,1608.25 7633.49,1781.66 8158.07,1781.66 8181.81,1757.92 8181.81,1457.66 8166.89,1442.74 v1(8130.77,1442.74)
  Bottom Layer w8: v1(8130.77,1442.74) 8165.05,1442.74 8190.6,1417.19 8190.6,1402.42 8220.58,1372.45 C129_A3.1@8224.52,1372.45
